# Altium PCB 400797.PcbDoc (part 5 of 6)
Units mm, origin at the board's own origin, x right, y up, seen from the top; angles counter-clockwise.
Board outline 155 x 63.5 mm, 4 copper layers (Top Layer, Mid-Layer 1, Mid-Layer 2, Bottom Layer), stack 1.514 mm thick; 317 components, 286 nets, 1519 pads, 2174 vias.
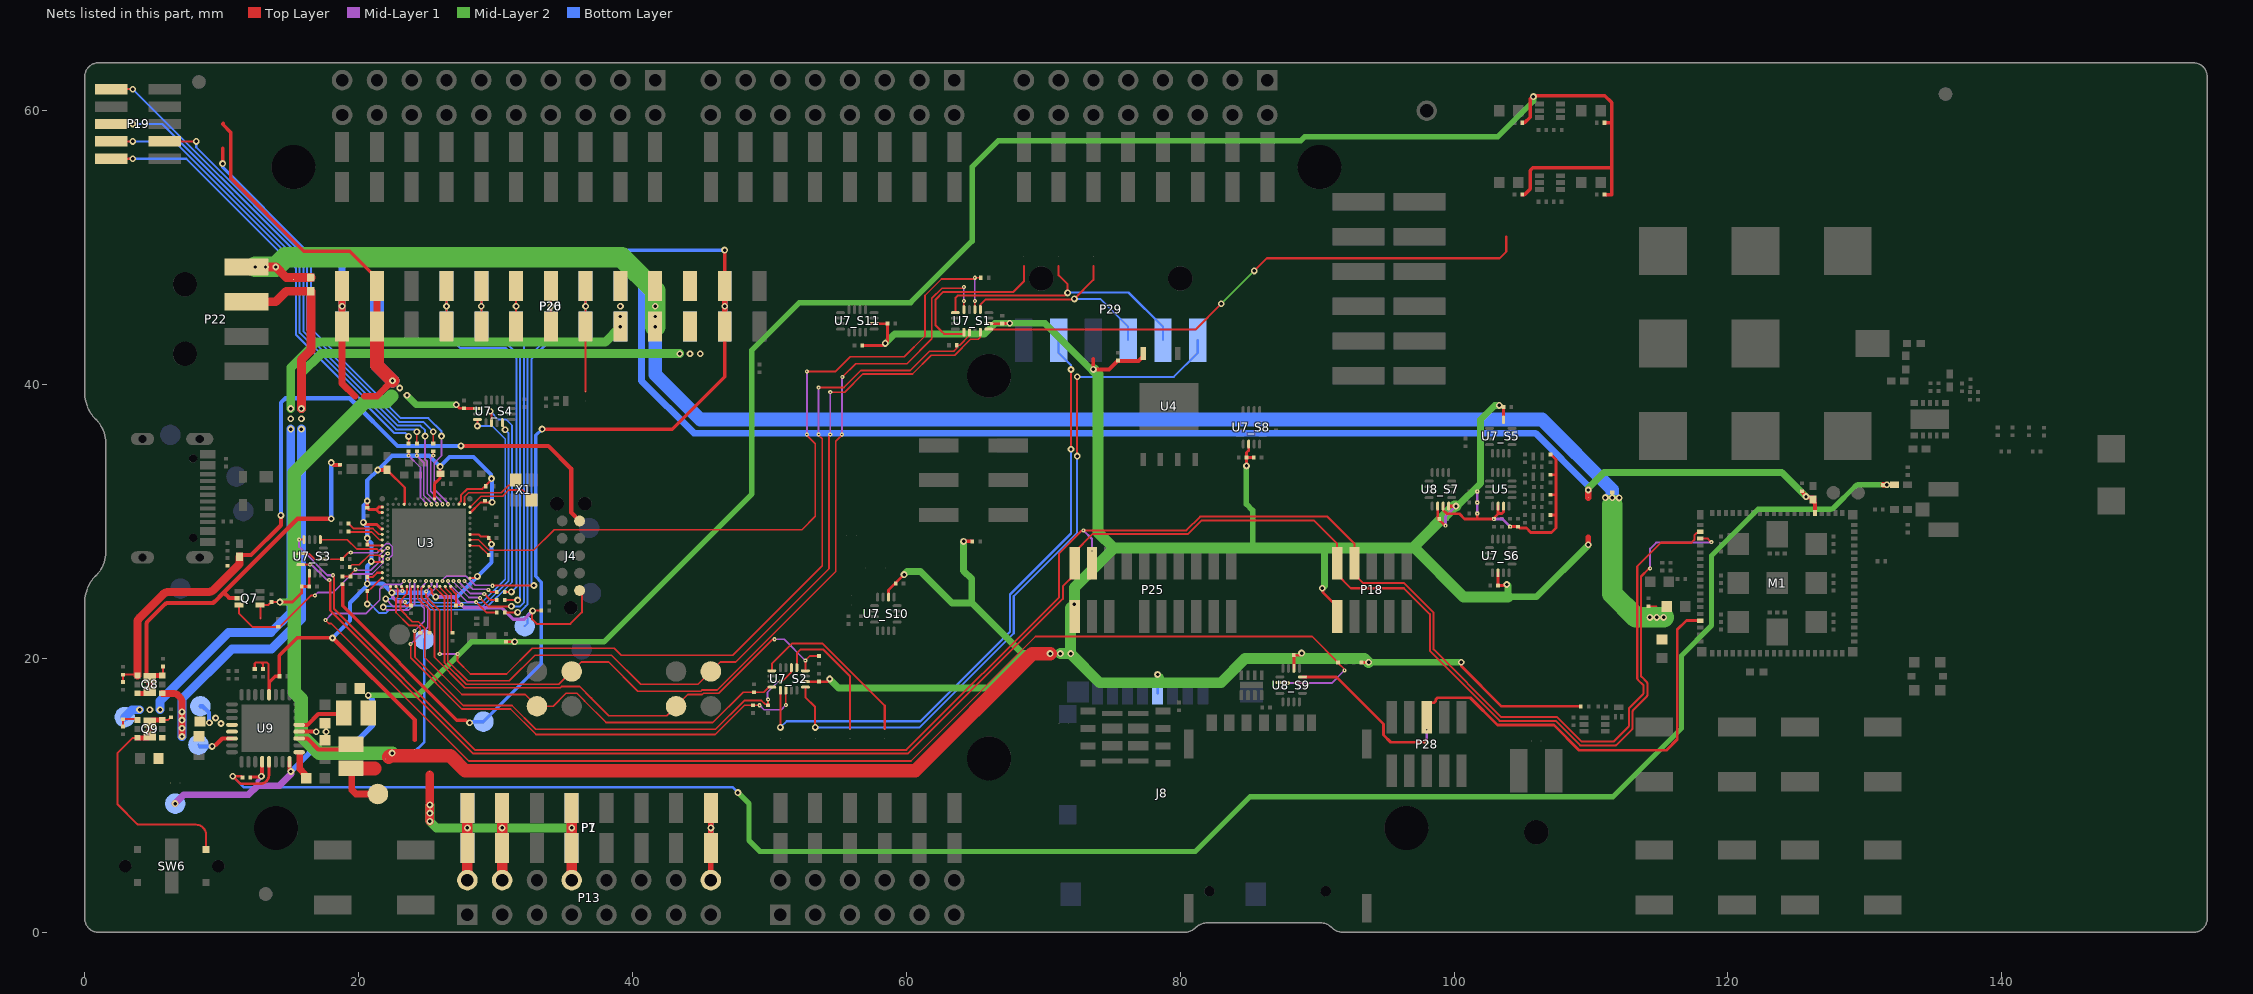
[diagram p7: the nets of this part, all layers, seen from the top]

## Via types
v1: diameter 0.5, hole 0.25, Top Layer to Bottom Layer, tented both sides, 1623 vias
v2: diameter 0.3, hole 0.1, Top Layer to Mid-Layer 1, tented top, 445 vias
v3: diameter 0.3, hole 0.1, Top Layer to Mid-Layer 1, tented both sides, 97 vias
v4: diameter 0.61, hole 0.305, Top Layer to Bottom Layer, tented both sides, 9 vias

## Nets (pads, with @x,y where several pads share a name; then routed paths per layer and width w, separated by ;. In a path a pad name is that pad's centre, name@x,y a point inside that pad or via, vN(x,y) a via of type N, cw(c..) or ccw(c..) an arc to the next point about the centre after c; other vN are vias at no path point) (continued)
SIM_RST: M1.16 P28.6 U8_S9.12 | length 43.8
  Top Layer w0.203: U8_S9.12@88.925,18.65 91.403,18.65 94.853,15.2 94.853,14.406 95.377,13.883 97.874,13.883 97.883,13.873 97.925,13.873 97.974,13.825 v2(98,13.825) ; P28.6@98,15.7 98,16.482 98.278,16.76 98.544,16.76 98.663,16.879 98.663,16.994 98.796,17.127 101.18,17.127 103.168,15.138 107.285,15.138 109.125,13.298 115.498,13.298 116.3,14.1 116.3,22.1 116.974,22.774 117.952,22.774 M1.16@117.975,22.75
  Mid-Layer 1 w0.203: v2(98,13.825) v2(98,14.8)
SIM_SELECT: R63.1 U3.AK8 U8_S9.2 | length 96.1
  Top Layer w0.125: v2(17.575,22.8) 17.825,22.55 18.004,22.55 28.041,12.513 60.337,12.513 69.426,21.602 89.628,21.602 91.552,19.678 91.552,19.648 91.967,19.233 91.967,19.158 v2(92,19.125) ; U8_S9.2@87.275,18.25 87.8,18.25 v2(87.85,18.2)
  Mid-Layer 1 w0.125: v2(17.575,22.8) 18.063,23.288 20.557,23.288 21.537,24.269 21.537,25.046 21.892,25.4 23.066,25.4 v2(23.325,25.659) ; v2(87.85,18.2) 91.075,18.2 v2(92,19.125)
SW1: L7.2 U9.3 | length 4.4
  Top Layer w0.3: U9.3@15.65,14.15 16.25,14.15 17.05,13.35 19.04,13.35 19.45,13.76 L7.2@19.5,13.76
SW2: L8.2 U9.5 | length 3.6
  Top Layer w0.3: U9.5@15.65,15.15 16.25,15.15 17.05,15.95 18.865,15.95 L8.2@18.915,16
SWD0.RESET: P19.10 R30.2 | length 37.6
  Top Layer w0.125: R30.2@25.45,35.694 v1(25.45,36.55)
  Top Layer w0.15: P19.10@1.936,61.571 v1(3.505,61.571)
  Bottom Layer w0.15: v1(3.505,61.571) 16.235,48.84 16.235,44.001 22.961,37.275 24.725,37.275 v1(25.45,36.55)
SWD0.SWDCLK: P19.4 R29.2 | length 34.8
  Top Layer w0.125: R29.2@24.25,35.694 v1(24.25,36.55)
  Top Layer w0.15: P19.4@1.936,57.761 v1(3.505,57.761)
  Bottom Layer w0.15: v1(3.505,57.761) 6.537,57.761 15.685,48.613 15.685,43.773 22.733,36.725 24.075,36.725 v1(24.25,36.55)
SWD0.SWDIO: P19.2 R28.2 | length 33.5
  Top Layer w0.125: R28.2@23.65,35.694 v1(23.65,36.219)
  Top Layer w0.15: P19.2@1.936,56.491 v1(3.505,56.491)
  Bottom Layer w0.15: v1(3.505,56.491) 7.418,56.491 15.41,48.499 15.41,43.659 22.619,36.45 23.419,36.45 v1(23.65,36.219)
SWD0_CLK: R29.1 U3.B18 | length 4.3
  Top Layer w0.125: v2(24.25,34.809) R29.1@24.25,35.124
  Mid-Layer 1 w0.125: v2(24.25,34.809) 24.762,34.297 24.762,31.897 25.063,31.597 25.065,31.597 25.262,31.399 25.262,31.397 25.325,31.334 v2(25.325,31.259)
SWD0_IO: R28.1 U3.B16 | length 4.4
  Top Layer w0.125: v2(23.65,34.809) R28.1@23.65,35.124
  Mid-Layer 1 w0.125: v2(23.65,34.809) 24.512,33.947 24.512,31.749 24.862,31.399 24.862,31.322 v2(24.925,31.259)
SWD0_RESET: R30.1 U3.B22 | length 4.3
  Top Layer w0.125: v2(25.45,34.809) R30.1@25.45,35.124
  Mid-Layer 1 w0.125: v2(25.45,34.809) 25.262,34.622 25.262,32.199 26.063,31.399 26.063,31.347 26.125,31.284 v2(26.125,31.259)
SWD0_SEL: P19.3 U3.B24 | length 38
  Top Layer w0.15: P19.3@5.836,57.761 v1(8.139,57.761)
  Mid-Layer 1 w0.125: v1(26.05,36.234) 26.05,34.809 25.512,34.272 25.512,32.349 26.462,31.399 26.462,31.322 v2(26.525,31.259)
  Bottom Layer w0.15: v1(8.139,57.761) 8.139,57.325 16.51,48.954 16.51,44.115 23.075,37.55 25.086,37.55 26.05,36.586 v1(26.05,36.234)
SWD0_SWO: P19.6 U3.B20 | length 40.8
  Top Layer w0.15: P19.6@1.936,59.031 v1(3.505,59.031)
  Mid-Layer 1 w0.125: v1(24.85,36.234) 24.85,34.563 25.012,34.4 25.012,32.049 25.662,31.399 25.662,31.347 25.725,31.284 v2(25.725,31.259)
  Bottom Layer w0.15: v1(3.505,59.031) 5.656,59.031 15.96,48.726 15.96,43.887 22.847,37 24.5,37 24.85,36.65 v1(24.85,36.234)
SWD1.RESET: P20.7 P26.7 R27.2 | length 28.8
  Top Layer w0.15: R27.2@30.66,23.359 v1(31.609,23.359) ; P20.7@34.036,44.256 v1(34.036,45.721) P20.7@34.036,47.186
  Bottom Layer w0.15: v1(31.609,23.359) 31.759,23.359 32.2,23.8 32.2,23.825 32.338,23.962 32.338,41.972 34.036,43.671 P26.7@34.036,44.256 v1(34.036,45.721) P26.7@34.036,47.186
SWD1.SWDCLK: P20.5 P26.5 R26.2 | length 29.3
  Top Layer w0.15: P20.5@28.956,43.689 P20.5@28.956,44.256 P20.5@28.956,47.186 ; R26.2@30.66,24.259 v1(31.609,24.259)
  Bottom Layer w0.15: P26.5@28.956,47.186 v1(28.956,45.721) 28.956,43.671 29.666,42.961 30.864,42.961 31.788,42.038 31.788,24.438 v1(31.609,24.259)
SWD1.SWDIO: P20.4 P26.4 R25.2 | length 29.9
  Top Layer w0.15: P20.4@26.416,44.349 P20.4@26.416,47.186 ; R25.2@30.66,24.859 v1(31.159,24.859)
  Bottom Layer w0.15: P26.4@26.416,47.186 v1(26.416,45.721) P26.4@26.416,44.256 26.416,43.671 27.401,42.686 30.75,42.686 31.513,41.924 31.513,25.213 v1(31.159,24.859)
SWD1_CLK: R26.1 U3.AK28 | length 3.4
  Top Layer w0.15: v2(29.176,24.71) 29.627,24.259 R26.1@30.09,24.259
  Mid-Layer 1 w0.125: v2(27.325,25.659) 27.325,25.612 27.387,25.549 27.387,25.519 28.16,24.747 29.015,24.747 29.019,24.744 29.143,24.744 v2(29.176,24.71)
SWD1_IO: R25.1 U3.AK30 | length 2.7
  Top Layer w0.15: v2(29.477,25.011) 29.628,24.859 R25.1@30.09,24.859
  Mid-Layer 1 w0.125: v2(27.725,25.659) 28.336,25.048 29.316,25.048 29.319,25.044 29.443,25.044 v2(29.477,25.011)
SWD1_RESET: R27.1 U3.AK24 | length 4.6
  Top Layer w0.15: v2(28.575,24.109) 29.325,23.359 R27.1@30.09,23.359
  Mid-Layer 1 w0.125: v2(26.525,25.659) 26.558,25.626 26.558,25.497 27.937,24.118 28.566,24.118 v2(28.575,24.109)
SWD1_SEL: P20.8 P26.8 SB17.2 U3.AK22 | length 39.5
  Top Layer w0.15: v2(29.777,25.311) 32.786,25.311 v1(32.8,25.325) ; SB17.2@36.576,39.486 SB17.2@36.576,39.498 P20.8@36.576,44.256 v1(36.576,45.721) P20.8@36.576,47.186
  Mid-Layer 1 w0.125: v2(26.125,25.659) 26.125,25.706 26.187,25.769 26.187,25.799 26.385,25.997 27.865,25.997 28.513,25.348 29.616,25.348
  Bottom Layer w0.15: v1(32.8,25.325) 32.613,25.513 32.613,41.859 33.715,42.961 35.866,42.961 36.576,43.671 P26.8@36.576,44.256 v1(36.576,45.721) P26.8@36.576,47.186
SWD1_SWO: P20.6 P26.6 U3.AK26 | length 32.8
  Top Layer w0.15: v2(28.876,24.41) 29.476,23.809 v1@31,23.809 ; P20.6@31.496,43.613 v1(31.496,45.721) P20.6@31.496,47.186
  Mid-Layer 1 w0.125: v2(26.925,25.659) 26.925,25.582 28.06,24.447 28.715,24.447 28.718,24.443 28.842,24.443 v2(28.876,24.41)
  Bottom Layer w0.15: v1(31.159,23.809) 31.795,23.809 32.063,24.076 32.063,43.105 31.496,43.671 P26.6@31.496,44.256 v1(31.496,45.721) P26.6@31.496,47.186
SWD3_CLK: R20.1 U3.R1 | length 2.7
  Top Layer w0.125: R20.1@19.26,29.259 19.26,29.244 19.27,29.234 20.946,29.234 21.521,28.659 U3.R1@21.725,28.659
SWD3_IO: R19.1 U3.N1 | length 2.8
  Top Layer w0.125: R19.1@19.26,29.859 19.26,29.844 19.333,29.772 19.348,29.772 19.635,29.484 21.05,29.484 21.475,29.059 U3.N1@21.725,29.059
SWD3_RESET: R22.1 U3.AA1 | length 2.8
  Top Layer w0.125: R22.1@19.36,26.684 19.514,26.838 20.056,26.838 20.758,27.54 21.444,27.54 21.525,27.459 U3.AA1@21.725,27.459
SWD3_SWO: U3.W1 U7_S3.5 | length 4.9
  Top Layer w0.125: U7_S3.5@17.2,28.675 19.174,28.675 19.852,27.997 21.341,27.997 21.479,27.859 U3.W1@21.725,27.859
SWD_CTRL: R24.2 U3.AB2 U7_S3.2 U7_S3.10 | length 8.5
  Top Layer w0.125: U7_S3.10@15.775,27.65 16.4,27.65 16.8,27.25 U7_S3.2@17.425,27.25 18.765,27.25 19.24,27.725 v2(19.425,27.725)
  Mid-Layer 1 w0.125: v2(19.425,27.725) 21.349,27.725 21.996,28.372 22.254,28.372 22.45,28.176 22.45,27.542 22.167,27.259 v2(22.125,27.259)
SWDCLK: M1.3 P18.4 P25.4 U7_S3.8 | length 144.5
  Top Layer w0.15: v2(15.65,28.675) U7_S3.8@16,28.675 ; v2(18.125,26.075) 18.154,26.046 18.154,25.916 18.2,25.87 18.2,23.616 28.491,13.325 60,13.325 71.15,24.475 71.15,27.678 72.792,29.32 72.898,29.32 v2(72.927,29.348) 80.446,29.348 81.45,30.353 90.752,30.353 92.73,28.375 P18.4@92.73,26.95 92.73,26.13 93.335,25.525 96.317,25.525 98.5,23.342 98.5,20.662 103.447,15.715 107.524,15.715 109.314,13.925 111.588,13.925 ccw(c111.588,14.075) 111.694,13.969 112.721,14.996 ccw(c112.615,15.102) 112.765,15.102 112.765,16.303 cw(c112.915,16.303) 112.809,16.409 113.797,17.397 ccw(c113.69,17.503) 113.84,17.503 113.84,17.972 ccw(c113.69,17.972) 113.797,18.078 113.419,18.456 cw(c113.525,18.562) 113.375,18.562 113.375,26.726 115.099,28.45 117.333,28.45 117.55,28.668 117.55,28.82 117.55,28.983 117.742,29.175 117.9,29.175 M1.3@117.975,29.25
  Mid-Layer 1 w0.15: v2(15.65,28.675) 15.65,28.145 17.72,26.075 v2(18.125,26.075) ; v2(72.927,29.348) 73.555,28.72 v2(73.555,27.85)
SWDIO: M1.4 P18.2 P25.2 U7_S3.12 | length 142.7
  Top Layer w0.15: U7_S3.12@15.775,26.85 v2@16.375,26.85 ; v2(16.45,26.85) v2@16.375,26.85 ; v2@16.45,26.925 v2@16.375,26.85 ; v2(17.85,25.725) 17.85,25.684 17.925,25.609 17.925,23.502 28.377,13.05 60.114,13.05 71.425,24.361 71.425,25.27 72.285,26.13 P25.2@72.285,26.95 72.285,27.77 73.588,29.073 80.559,29.073 81.564,30.078 89.757,30.078 91.46,28.375 P18.2@91.46,26.95 91.46,26.13 92.465,25.125 96.328,25.125 98.225,23.228 98.225,20.548 103.333,15.44 107.41,15.44 109.2,13.65 111.763,13.65 ccw(c111.763,13.8) 111.869,13.694 112.996,14.821 ccw(c112.89,14.927) 113.04,14.927 113.04,14.995 113.04,16.128 cw(c113.19,16.128) 113.084,16.234 114.072,17.222 ccw(c113.965,17.328) 114.115,17.328 114.115,18.172 ccw(c113.965,18.172) 114.072,18.278 ; 114.072,18.278 113.694,18.656 cw(c113.8,18.762) 113.65,18.762 113.65,25.983 114.217,26.55 114.292,26.55 v3(114.321,26.579) ; M1.4@117.975,28.75 118.528,28.75 v3(118.786,28.491)
  Mid-Layer 1 w0.15: v2(16.45,26.85) 16.556,26.85 17.656,25.75 17.825,25.75 v2(17.85,25.725) ; v3(114.321,26.579) 114.321,28.021 114.763,28.463 118.758,28.463 v3(118.786,28.491)
TGT_SCL: U3.AK12 U7_S4.4 | length 26.2
  Top Layer w0.125: U7_S4.4@30.5,37.225 30.5,36.984 30.7,36.784 v1(30.7,36.7)
  Mid-Layer 1 w0.125: v1(21.8,23.75) 22.013,23.538 23.665,23.538 24.075,23.947 24.075,25.609 v2(24.125,25.659)
  Bottom Layer w0.125: v1(21.8,23.75) 21.857,23.807 23.311,23.807 23.617,24.113 25.034,24.113 25.34,23.807 29.078,23.807 30.95,25.679 30.95,36.439 30.7,36.689 v1(30.7,36.7)
TGT_SDA: U3.AK10 U7_S4.16 | length 26.5
  Top Layer w0.125: v1(28.675,36.975) U7_S4.16@28.675,37.45
  Mid-Layer 1 w0.125: v1(21.975,24.35) 22.538,23.788 23.541,23.788 23.725,23.971 v2(23.725,25.659)
  Bottom Layer w0.125: v1(21.975,24.35) 23.501,24.35 23.514,24.363 25.138,24.363 25.444,24.057 28.974,24.057 30.7,25.782 30.7,36.025 29.75,36.975 v1(28.675,36.975)
TGT_TWI_CTRL: R31.1 U3.AJ1 U7_S4.2 | length 28.8
  Top Layer w0.125: v1(20.625,23.975) 20.635,23.985 20.635,24.85 21.063,25.278 21.643,25.859 U3.AJ1@21.725,25.859 ; v1(29.6,38.05) 29.7,37.95 U7_S4.2@29.7,37.225
  Bottom Layer w0.125: v1(20.625,23.975) 20.836,23.975 21.498,23.313 21.981,23.313 22.225,23.557 23.415,23.557 23.721,23.863 24.931,23.863 25.237,23.557 29.182,23.557 31.2,25.575 31.2,37.025 30.775,37.45 30.2,37.45 v1(29.6,38.05)
UART1.CTS: P29.6 SB6.2 U7_S2.13 | length 51.7
  Top Layer w0.15: U7_S2.13@52.625,17.9 52.625,17.17 53.34,16.455 v1(53.34,14.962) ; v1(72.475,34.775) v1(72.475,40.566)
  Bottom Layer w0.15: v1(53.34,14.962) 60.967,14.962 67.842,21.837 67.842,24.554 72.475,29.186 v1(72.475,34.775) ; v1(72.475,40.566) 79.541,40.566 81.28,42.305 P29.6@81.28,43.25
UART1.RTS: P29.2 SB5.2 U7_S2.9 | length 46.2
  Top Layer w0.15: SB5.2@50.8,14.838 SB5.2@50.8,14.85 v1(50.8,14.962) U7_S2.9@50.8,17.675 U7_S2.9@50.8,17.875 ; v1(72.025,35.275) v1(72.025,41.1)
  Bottom Layer w0.15: v1(50.8,14.962) 51.25,15.412 61.028,15.412 67.567,21.951 67.567,24.667 72.025,29.125 v1(72.025,35.275) ; P29.2@71.12,43.25 71.12,42.305 72.025,41.4 v1(72.025,41.1)
UART1.RXD: P29.4 SB3.2 U7_S1.1 | length 16.1
  Top Layer w0.15: U7_S1.1@65.4,45.475 65.4,45.818 65.807,46.225 72.24,46.225 v1(72.268,46.253) 73.66,47.645 SB3.2@73.66,48.65 SB3.2@73.66,48.662
  Bottom Layer w0.15: v1(72.268,46.253) 74.172,46.253 74.221,46.204
  Bottom Layer w0.152: 74.221,46.204 76.2,44.225 P29.4@76.2,43.25
UART1.TXD: P29.5 SB4.2 U7_S1.5 | length 20.6
  Top Layer w0.15: U7_S1.5@63.575,45.25 63.575,46.325 63.75,46.5 71.575,46.5 v1(71.775,46.7) 71.775,47.325 71.12,47.98 SB4.2@71.12,48.662
  Bottom Layer w0.15: v1(71.775,46.7) 71.8,46.725 76.225,46.725 78.74,44.21 P29.5@78.74,43.25
UART2.CTS: SB10.2 U7_S2.5 | length 13
  Top Layer w0.15: U7_S2.5@50.175,19.1 50.175,19.623 51.652,21.1 53.864,21.1 58.42,16.544 SB10.2@58.42,14.85 SB10.2@58.42,14.838
UART2.RTS: SB9.2 U7_S2.1 | length 9.7
  Top Layer w0.15: U7_S2.1@52,19.325 52,20.375 52.288,20.663 53.912,20.663 55.88,18.695 SB9.2@55.88,14.85 SB9.2@55.88,14.838
UART2.RXD: SB7.2 U7_S1.9 | length 12.4
  Top Layer w0.15: U7_S1.9@64.2,43.825 64.2,43.74 64.162,43.702 62.755,43.702 62.55,43.907 62.55,43.914 62.125,44.339 62.125,46.194 62.706,46.775 67.825,46.775 68.58,47.53 SB7.2@68.58,48.65 SB7.2@68.58,48.662
UART2.TXD: SB8.2 U7_S1.13 | length 41.2
  Top Layer w0.15: U7_S1.13@66.025,44.05 66.05,44.025 81.125,44.025 v1(83,45.9) ; v1(85.4,48.3) 86.325,49.225 103.325,49.225 103.81,49.71 SB8.2@103.81,50.801
  Mid-Layer 2 w0.15: v1(83,45.9) v1(85.4,48.3)
USB_DETECT: Q7.3 R74.2 SB29.2 U3.Y2 | length 14.4
  Top Layer w0.15: Q7.3@11.25,23.9 11.25,23.311 12.274,22.288 13.178,22.288 R74.2@14.125,22.288 ; R74.2@14.125,22.315 14.24,22.315 16.525,24.6 v2(16.8,24.6)
  Mid-Layer 1 w0.125: v2(16.8,24.6) 17.012,24.812 18.157,24.812 19.507,26.163 20.972,26.163 21.775,26.966 21.775,27.433 22.001,27.659 v2(22.125,27.659)
VBUS: Q7.2 Q8.3 Q8.6 R21.1 R78.2 | length 30.4
  Top Layer w0.15: Q8.6@5.655,18.75 5.7,18.795 R78.2@5.7,19.415
  Top Layer w0.3: Q8.6@4.75,18.575 4.5,18.825 4.5,22.476 cw(c4.8,22.476) 4.588,22.688 5.862,23.962 cw(c6.074,23.75) 6.074,24.05 9.268,24.05 ccw(c9.268,24.35) 9.48,24.138 10.148,24.805 ; Q7.2@11.25,24.4 10.553,24.4 10.148,24.805 ; v1(18,30.2) 15.542,30.2 10.148,24.805 ; v1(18,34.3) 18.165,34.135 R21.1@18.625,34.135
  Top Layer w0.35: Q8.3@3.845,17.45 4.575,17.45 Q8.3@4.75,17.625 ; Q8.6@4.75,18.575 4.925,18.75 Q8.6@5.655,18.75
  Top Layer w0.5: Q8.3@4.75,17.625 Q8.6@4.75,18.575
  Bottom Layer w0.3: v1(18,30.2) v1(18,34.3)
VBUS': C51.2 FB2.2 J4.5 Q8.1 R76.1 R77.1 | length 55.7
  Top Layer w0.15: R77.1@2.8,18.285 R76.1@2.8,18.815 Q8.1@3.78,18.815
  Top Layer w0.2: Q8.1@3.78,18.815 Q8.1@3.845,18.75
  Top Layer w0.3: FB2.2@11.3,27.425 11.3,27.45 11.4,27.55 12.15,27.55 14.325,29.725 v1(14.325,30.45) ; v1(27.475,35.525) 33.85,35.525 35.525,33.85 35.525,30.65 J4.5@36.135,30.04
  Top Layer w0.6: Q8.1@3.845,18.75 3.845,22.571 cw(c4.445,22.571) 4.02,22.995 5.7,24.675 cw(c6.124,24.25) 6.124,24.85 9.001,24.85 ccw(c9.001,25.45) 9.426,25.026 11.3,26.9 FB2.2@11.3,27.425
  Bottom Layer w0.3: v1(14.325,30.45) 14.325,38.675 14.65,39 19.35,39 22.825,35.525 v1(27.475,35.525)
VBUSOUT: TP25.1 U9.22 | length 2.4
  Top Layer w0.3: 9.564,13.675 10.039,14.15 U9.22@10.75,14.15
  Bottom Layer w0.15: TP25.1@8.3,13.7 TP25.1@8.425,13.575
  Bottom Layer w0.3: TP25.1@8.425,13.575 v1(9.3,13.575)
VCOM0_CTRL: R13.1 U3.R31 U7_S1.2 | length 57
  Top Layer w0.125: U3.R31@28.125,28.659 28.754,28.659 29.516,27.896 32.771,27.896 34.275,29.4 52.375,29.4 53.35,30.375 53.35,35.685 52.737,36.298 v2(52.737,36.35) ; v2(52.737,40.963) 54.841,40.963 55.904,42.025 59.839,42.025 61.362,43.548 61.362,46.509 62.566,47.713 64.913,47.713 v2(65,47.8) R13.1@65.44,47.8 ; U7_S1.2@65,45.475 v2(65,46.1)
  Mid-Layer 1 w0.125: v2(52.737,36.35) v2(52.737,40.963) ; v2(65,46.1) v2(65,47.8)
VCOM0_CTS: R86.1 TP5.1 U3.AL9 U7_S2.8 | length 35.9
  Top Layer w0.125: U3.AL9@23.525,25.259 23.525,24.717 23.062,24.254 23.062,23.548 23.923,22.688 24.366,22.688 24.838,22.216 24.838,20.072 27.547,17.363 32.168,17.363 32.822,16.708 32.822,16.312 TP5.1@33.02,16.51 34.201,16.51 35.139,17.448 35.948,17.448 36.498,16.898 36.498,16.895 38.07,15.323 45.858,15.323 48.076,17.54 R86.1@48.875,17.54 49.59,17.54 49.95,17.9 U7_S2.8@50.175,17.9
VCOM0_HWFC: R17.1 U3.AK16 U7_S2.2 | length 38.7
  Top Layer w0.125: v2(24.075,22.004) 24.075,21.217 24.113,21.179 24.113,20.09 27.64,16.563 31.198,16.563 32.938,14.823 46.065,14.823 48.165,16.923 49.425,16.923 49.69,16.658 49.828,16.658 R17.1@49.9,16.585 v2(49.9,17) ; v2(50.8,18.3) 50.9,18.3 51.6,19 U7_S2.2@51.6,19.325
  Mid-Layer 1 w0.125: v2(24.075,22.004) 24.788,22.716 24.788,23.658 24.587,23.858 24.587,25.237 24.853,25.503 24.853,25.54 24.925,25.612 v2(24.925,25.659) ; v2(49.9,17) 49.862,17.038 49.862,17.54 50.623,18.3 v2(50.8,18.3)
VCOM0_RTS: R15.1 U3.AL5 | length 4.6
  Top Layer w0.125: U3.AL5@22.725,25.259 22.725,25.235 22.862,25.097 22.862,24.488 22.725,24.35 22.725,23.351 23.663,22.413 24.288,22.413 24.5,22.2 R15.1@24.5,21.869
VCOM0_RXD: TP4.1 U3.AL19 U7_S1.4 | length 69.7
  Top Layer w0.125: U3.AL19@25.525,25.217 25.542,25.217 26.262,24.497 26.262,20.465 26.263,20.185 26.262,19.708 27.858,18.113 34.622,18.113 TP4.1@35.56,19.05 36.248,19.738 38.262,19.738 40.388,17.613 44.991,17.613 45.076,17.698 46.194,17.698 54.85,26.354 54.85,35.86 55.288,36.298 v2(55.288,36.35) ; v2(55.325,40.55) 56.3,41.525 60.046,41.525 61.862,43.341 61.862,46.302 62.598,47.038 64.088,47.038 v2@64.175,47.125 ; U7_S1.4@64.2,45.475 v2(64.2,46.1)
  Top Layer w0.15: U3.AL19@25.525,25.217 U3.AL19@25.525,25.259
  Mid-Layer 1 w0.125: v2(55.288,36.35) 55.306,36.369 55.306,40.531 v2(55.325,40.55) ; v2@64.175,47.125 64.2,47.1 v2(64.2,46.1)
  other v2: 64.2,47.125
VCOM0_TXD: R11.1 U3.U31 | length 1.7
  Top Layer w0.125: U3.U31@28.125,28.259 28.144,28.24 28.819,28.24 R11.1@29.5,27.559
VCOM1_CTRL: R14.2 U3.AK18 U7_S1.10 | length 64.5
  Top Layer w0.125: v2@24.925,24.925 v2(24.925,24.9) 24.925,24.475 25.925,23.475 v2(25.925,20.325) ; v2(27.225,20.325) 27.225,19.806 28.169,18.863 30.8,18.863 32.675,20.738 38.677,20.738 39.177,20.238 47.32,20.238 53.85,26.768 53.85,36.035 53.588,36.298 v2(53.588,36.35) ; v2@53.588,39.75 53.625,39.788 55.438,39.788 56.675,41.025 60.275,41.025 61.688,42.438 63.459,42.438 63.661,42.639 63.661,42.851 R14.2@63.685,42.875 63.886,42.875 64.6,43.589 U7_S1.10@64.6,43.825
  Mid-Layer 1 w0.125: v2@24.925,24.925 25.325,25.325 v2(25.325,25.659) ; v2(25.925,20.325) v2(27.225,20.325) ; v2(53.588,36.35) v2(53.588,39.775)
VCOM1_CTS: R85.1 TP9.1 U3.AL15 U7_S2.16 | length 39.4
  Top Layer w0.125: U3.AL15@24.725,25.259 24.725,25.235 24.575,25.085 24.575,24.471 25.538,23.509 25.538,20.079 27.754,17.863 34.726,17.863 34.811,17.948 36.152,17.948 36.155,17.948 36.998,17.105 36.998,17.102 38.277,15.823 42.492,15.823 TP9.1@43.18,16.51 44.032,17.363 45.095,17.363 45.18,17.448 46.298,17.448 50.25,21.4 v2(50.375,21.4) ; v2(52.625,19.85) 52.96,20.185 R85.1@53.625,20.185
  Top Layer w0.15: U7_S2.16@52.625,19.1 v2(52.625,19.85)
  Mid-Layer 1 w0.125: v2(50.375,21.4) 51.075,21.4 v2(52.625,19.85)
VCOM1_HWFC: R18.2 U3.AK20 U7_S2.10 | length 38.4
  Top Layer w0.125: v2(23.8,21.05) 23.8,20.049 27.537,16.313 31.095,16.313 32.957,14.45 46.046,14.45 48.181,16.585 v2(49.285,16.585) ; v2(51.2,16.6) U7_S2.10@51.2,17.675
  Mid-Layer 1 w0.125: v2(23.8,21.05) 25.038,22.288 25.038,24.535 25.725,25.223 v2(25.725,25.659) ; v2(49.285,16.585) 49.608,16.263 50.862,16.263 v2(51.2,16.6)
VCOM1_RTS: R16.1 U3.AL13 | length 3.7
  Top Layer w0.125: U3.AL13@24.325,25.259 24.325,24.368 25.175,23.518 R16.1@25.175,21.869
VCOM1_RXD: TP8.1 U3.AL21 U7_S1.12 | length 65.2
  Top Layer w0.125: U3.AL21@25.925,25.235 25.925,25.188 25.976,25.138 ; 25.976,25.137 26.512,24.6 26.512,20.568 26.513,20.082 26.512,19.811 27.961,18.363 31.007,18.363 32.882,20.238 38.47,20.238 40.595,18.113 44.782,18.113 TP8.1@45.72,19.05 46.408,19.738 47.527,19.738 54.35,26.561 54.35,36.263 v2(54.438,36.35) ; v2(54.438,39.45) 55.5,39.45 56.825,40.775 60.45,40.775 61.825,42.15 63.525,42.15 64.687,43.313 65.257,43.313 65.4,43.455 U7_S1.12@65.4,43.825
  Mid-Layer 1 w0.125: v2(54.438,36.35) v2(54.438,39.45)
VCOM1_TXD: R12.1 U3.AL23 | length 3.6
  Top Layer w0.125: U3.AL23@26.325,25.259 26.344,25.24 26.344,25.122 26.762,24.704 26.762,21.932 R12.1@26.825,21.869
VDD: C42.2 C52_S1.1 C52_S2.1 C52_S3.1 C52_S4.1 C52_S5.1 C52_S6.1 C52_S8.1 C52_S10.1 C52_S11.1 C53_S7.1 C53_S9.1 J8.4 P18.1 P20.2 P25.1 P26.2 Q7.4 R8.1 R23.2 R35.2 R62.1 R66.1 R69.2 R75.1 SB1.1 SB16.2 SB20.1 SB29.1 SB30.2 SB31.1 SB32.1 SB33.2 TP23.1 U4.8 U7_S1.14 U7_S2.14 U7_S3.14 U7_S4.14 U7_S5.14 U7_S6.14 U7_S8.14 U7_S10.14 U7_S11.14 U8_S7.14 U8_S7.16 U8_S9.14 | length 355.1
  Top Layer w0.15: 12.825,22.912 SB29.1@12.825,22.95 12.825,23.875 Q7.4@12.8,23.9 13.41,23.9 R75.1@13.625,24.115 v1(14.25,24.115)
  Top Layer w0.2: v1(14.25,24.115) 15.165,24.115 15.835,24.785 C52_S3.1@15.835,25.25 R23.2@16.335,25.25 ; R23.2@16.39,25.25 R23.2@16.335,25.25 ; U7_S3.14@16.4,26.225 16.4,25.315 R23.2@16.335,25.25 ; v1(27.125,38.525) 27.385,38.265 C52_S4.1@27.7,38.265 27.715,38.25 U7_S4.14@28.675,38.25 ; U7_S2.14@52.625,18.3 54.2,18.3 v1(54.4,18.5) ; R66.1@56.785,42.85 58.3,42.85 v1(58.458,43.008) 58.615,43.165 C52_S11.1@58.615,44.45 U7_S11.14@57.643,44.45 ; U7_S10.14@58.7,24.475 58.7,24.993 v1(59.832,26.125) ; U7_S1.14@66.025,44.45 66.985,44.45 C52_S1.1@67,44.465 67.54,44.465 v1(67.55,44.475) ; v1(84.838,34.062) C52_S8.1@84.838,34.671 ; U7_S8.14@85,35.65 85,35.193 84.838,35.031 C52_S8.1@84.838,34.671 ; R35.2@85.368,34.671 C52_S8.1@84.838,34.671 ; U8_S9.14@88.3,19.275 88.3,20.235 v1@88.86,20.235 ; v1(90.375,25.125) 90.432,25.068 90.432,24.818 91.46,23.79 P18.1@91.46,23.05 ; R62.1@93.235,19.7 v1@93.752,19.7 ; U8_S7.14@98.8,31.125 98.8,30.225 99.325,29.7 v2(99.375,29.7) v2@99.4,29.7 ; v1(100.525,19.718) 100.525,19.45 103.475,16.5 R8.1@109.255,16.5 ; U7_S6.14@103.21,26.259 103.208,26.257 C52_S6.1@103.208,25.334 103.217,25.325 103.775,25.325 v1(103.85,25.4)
  Top Layer w0.22: v1(103.3,38.475) 103.376,38.475 103.452,38.399 103.588,38.399 103.61,38.377 U7_S5.14@103.61,37.434
  Top Layer w0.25: v1(73.66,41.11) SB20.1@73.66,41.855 73.66,41.893
  Top Layer w0.254: SB16.2@10.1,59.095 10.062,59.057 10.062,59 10.675,58.387 10.675,55.075 16,49.75 19.35,49.75 21.336,47.764 P20.2@21.336,46.949 ; v1(64.176,28.55) R69.2@64.815,28.55 ; U8_S7.16@99.6,31.125 v1(100.137,31.125)
  Top Layer w0.3: v1(73.66,41.11) 74.795,41.11 75.41,41.725 76.95,41.725 77.282,42.057 U4.8@77.282,42.27
  Top Layer w0.4: v1(109.8,28.3) SB1.1@109.8,28.85
  Top Layer w0.5: 20.404,39.148 21.337,39.148 v1(22.47,40.28)
  Top Layer w0.508: P20.2@21.336,44.256 P20.2@21.336,46.949
  Top Layer w1: P20.2@21.336,44.256 21.336,41.414 v1(22.47,40.28) ; 22.2,12.8 22.3,12.9 25.195,12.9 26.678,12.9 27.778,11.8 60.65,11.8 69.2,20.35 v1(70.5,20.35)
  Mid-Layer 1 w0.2: v2(99.375,29.7) 99.375,30.363 v1(100.137,31.125)
  Mid-Layer 2 w0.4: v1(84.838,34.062) 84.838,31.265 85.282,30.821 85.282,28.05
  Mid-Layer 2 w0.5: v1(14.25,24.115) 15.29,24.115 15.3,24.125 ; v1(23.53,39.22) 24.225,38.525 v1(27.125,38.525) ; v1(54.4,18.5) 55.05,17.85 65.975,17.85 68.475,20.35 ; v1(58.458,43.008) 59.15,43.7 65.7,43.7 66.475,44.475 v1(67.55,44.475) 70.125,44.475 73.49,41.11 v1(73.66,41.11) ; v1(59.832,26.125) 60.057,26.35 61.025,26.35 63.325,24.05 64.775,24.05 ; v1(64.176,28.55) 64.176,26.399 64.775,25.8 64.775,24.05 ; v1(70.5,20.35) 68.475,20.35 ; v1(78.35,18.825) 78.58,18.595 78.58,18.225 ; v1(88.86,20.385) 89.13,20.115 89.13,20 ; v1(90.375,25.125) 90.53,25.28 90.53,28.05 ; v1(93.752,19.718) v1(100.525,19.718) ; v1(100.137,31.125) 100.259,31.125 101.925,32.791 101.925,37.431 102.969,38.475 v1(103.3,38.475) ; v1(103.85,25.4) 103.93,25.32 103.93,24.5 106,24.5 v1(109.8,28.3) ; 64.775,24.05 68.475,20.35
  Mid-Layer 2 w0.8: v1(71.25,20.35) 71.975,20.35 74.1,18.225 78.58,18.225 82.968,18.225 84.743,20 89.13,20 93.47,20 v1(93.752,19.718) ; v1(72,20.35) 72,23.675 v1(72.275,23.95) 72.275,25.17 75.155,28.05 ; v1(73.66,41.11) 74,40.77 74,29.205 75.155,28.05 ; v1(100.137,31.125) 100.025,31.125 96.95,28.05 ; 103.93,24.5 100.693,24.5 97.143,28.05 96.95,28.05 ; 75.155,28.05 85.282,28.05 90.53,28.05 96.95,28.05
  Mid-Layer 2 w1: 22.4,39.15 22,38.75 20.5,38.75 15.3,33.55 15.3,24.125 15.3,17.543 15.8,17.043 15.8,14.4 17.116,13.084 v1(22.444,13.084)
  Bottom Layer w0.2: v1(22.444,13.084) 22.616,13.084 22.62,13.08 23.354,13.08 23.358,13.084 23.984,13.084 24.795,13.895 TP23.1@24.795,21.38 ; J8.4@78.35,17.47 v1(78.35,18.825)
  Bottom Layer w1: P26.2@21.336,47.186 P26.2@21.336,44.256 21.336,41.414 v1(22.47,40.28)
  other v1: 23,39.75
VDD_1V8: C60.2 L7.1 SB33.1 TP21.1 U9.1 | length 8.9
  Top Layer w0.3: U9.1@15.65,13.15 15.65,11.9 C60.2@16.275,11.275
  Top Layer w0.5: 15.7,12.9 15.7,11.92 C60.2@16.05,11.57 ; L7.1@19.45,11.965 19.5,11.915 19.5,10.393 19.793,10.1 TP21.1@21.4,10.1
  Top Layer w1: L7.1@19.45,11.965 21.165,11.965
VDD_3V0: C59.2 L8.1 R33.2 R39.2 R40.2 R41.2 R42.2 R87.1 TP27.1 U9.28 U9.32 | length 160
  Top Layer w0.2: R87.1@12.085,11.3 12.085,11.315 12.12,11.35 12.85,11.35 v1(12.9,11.4) ; R33.2@30.75,21.215 v1(31.39,21.215)
  Top Layer w0.25: R41.2@104.983,53.868 105.143,53.868 105.556,54.281 105.556,55.632 105.747,55.823 111.496,55.823 ; R39.2@104.983,59.118 105.143,59.118 105.556,59.531 105.556,60.882 ; v1(105.79,61.033) 105.856,61.1 111,61.1 111.499,60.601 111.499,53.868 R42.2@110.983,53.868 ; R40.2@110.983,59.118 111.499,59.118
  Top Layer w0.3: v1(12.9,11.4) 12.95,11.45 U9.28@12.95,12.45 ; U9.32@14.95,12.45 14.95,11.896 15.048,11.798 v1(15.048,11.744)
  Mid-Layer 1 w0.3: 12.6,10.7 12.6,11.046 12.9,11.346 v1(12.9,11.4)
  Mid-Layer 1 w0.5: v1(6.6,9.4) 7.25,10.05 11.95,10.05 12.6,10.7 14.184,10.7 15.048,11.564 v1(15.048,11.744)
  Mid-Layer 2 w0.4: v1(20.7,17.3) 24.313,17.3 28.228,21.215 v1(31.39,21.215) 37.915,21.215 48.714,32.014 48.714,42.514 52.189,45.989 60.311,45.989 64.8,50.479 64.8,55.9 66.7,57.8 88.8,57.8 89.1,58.1 103.2,58.1 105.8,60.7 105.8,61 105.79,61.01 v1(105.79,61.033)
  Bottom Layer w0.4: v1(15.048,11.744) 16.404,13.1 19,13.1 21,15.1 21,17 v1(20.7,17.3)
VDD_5V: C54.2 C58.2 P20.11 P22.2 P26.11 Q8.4 Q9.4 R82.2 SB34.2 SB35.1 U9.21 | length 76.7
  Top Layer w0.5: Q8.4@5.655,17.45 6.468,17.45 cw(c6.468,16.95) 6.821,17.304 6.954,17.171 cw(c6.6,16.818) 7.1,16.818 v1(7.1,16.1) v1(7.1,15.5) v1(7.1,14.9) v1(7.1,14.3)
  Top Layer w0.65: P22.2@11.811,46.049 13.946,46.049 14.716,46.819 R82.2@16.51,46.819 16.51,42.491 15.819,41.8 v1(15.819,38.25)
  Mid-Layer 2 w0.65: v1(15.819,38.25) 15.819,40.819 17.256,42.256 v1(43.446,42.256)
  Bottom Layer w0.65: v1(7.1,14.3) v1(7.1,14.9) v1(7.1,15.5) 7.1,15.903 7.1,17.04 10.76,20.7 13.651,20.7 15.819,22.867 v1(15.819,36.75)
  other v1: 15.819,37.5 44.196,42.256 44.946,42.256
VDD_GNSS: C11.2 L3.1 R87.2 U9.29 | length 147.6
  Top Layer w0.2: R87.2@11.515,11.3 11.415,11.4 v1(10.8,11.4) 10.9,11.3 11.291,10.909 ccw(c11.433,11.05) 11.433,10.85 12.825,10.85 ccw(c12.825,11.475) 13.45,11.475 U9.29@13.45,12.45 ; C11.2@131.315,32.68 C11.2@131.318,32.68 ; v1@131.66,32.68 L3.1@132.155,32.68
  Top Layer w0.381: C11.2@131.318,32.68 131.601,32.68 v1(131.606,32.685)
  Mid-Layer 2 w0.381: v1(47.7,10.2) 48.5,9.4 48.5,6.7 49.3,5.9 81.1,5.9 85.1,9.9 111.6,9.9 116.6,14.9 116.6,20.2 118.8,22.4 118.8,27.5 122.2,30.9 127.467,30.9 ccw(c127.467,31.281) 127.736,31.011 129.299,32.574 cw(c129.568,32.304) 129.568,32.685 v1(131.606,32.685)
  Bottom Layer w0.2: v1(10.8,11.4) 11.6,10.6 47.3,10.6 v1(47.7,10.2)
VDD_GPIO: C4.1 C5.1 M1.65 P20.1 P26.1 SB2.1 SB31.2 | length 136.1
  Top Layer w0.305: C4.1@125.4,32.185 125.602,31.983 125.602,31.97 125.7,31.872 v1(125.7,31.819) ; v1@125.691,31.8 125.753,31.8 125.805,31.748 126.202,31.748 126.3,31.65 126.3,31.4 126.35,31.35 M1.65@126.35,30.625
  Top Layer w0.5: 18.796,41.891 18.796,40.08 SB31.2@19.728,39.148 ; SB2.1@109.8,31.75 v1(109.8,32.3)
  Top Layer w0.508: 18.796,41.891 P20.1@18.796,44.256 P20.1@18.796,47.186
  Mid-Layer 2 w0.5: v1(109.8,32.3) 109.8,32.45 110.937,33.587 123.933,33.587 v1(125.7,31.819)
  Bottom Layer w0.5: P26.1@18.796,47.186 18.796,48.821 19.3,49.325 39.575,49.325 40.65,48.25 40.65,40.275 44.479,36.446 105.929,36.446 109.8,32.575 v1(109.8,32.3)
  Bottom Layer w0.508: P26.1@18.796,44.256 P26.1@18.796,47.186
  other v1: 18.796,45.721
VDD_IMCU: C24.2 C25.2 C26.1 C27.2 C28.1 C31.2 C32.2 C33.2 C34.1 C35.2 C62.1 J4.1 R34.2 R83.2 R84.2 SB32.2 TP12.1 U3.A19 U3.AC1 U3.AG1 U3.AJ31 U3.AL3 U3.AL7 U3.AL11 U3.AL17 U3.AL25 U3.B8 U3.B28 U3.C1 U3.E1 U3.E31 U3.L1 U3.N31 U3.U1 U9.12 | length 105
  Top Layer w0.15: R84.2@12.412,19.227 12.412,19.612 12.5,19.7 12.9,19.7 ; R83.2@13.012,19.227 13.012,19.588 12.9,19.7 ; 13.46,18.26 13.4,18.319 13.4,19.6 13.3,19.7 12.9,19.7 ; v1@20.635,25.459 C26.1@20.635,25.959 ; C25.2@20.635,28.259 U3.U1@21.725,28.259 ; C25.2@20.635,28.334 v1@20.635,28.784 ; C26.1@20.65,25.959 21.05,25.959 21.35,26.259 U3.AG1@21.725,26.259 ; v1@20.925,27.059 U3.AC1@21.725,27.059 ; v1@22.325,24.794 U3.AL3@22.325,25.259 ; v2(23.2,24.923) U3.AL7@23.2,25.184 ; v2(23.375,24.125) 23.375,24 23.506,23.869 C27.2@23.827,23.869 23.838,23.88 23.838,25.151 23.925,25.239 U3.AL11@23.925,25.259 ; U3.AL17@25.125,25.217 25.34,25.002 25.34,24.779 v1(25.625,24.494) ; U3.AL25@26.725,25.259 26.725,25.113 27.1,24.738 C31.2@27.1,23.869 27.125,23.894 27.475,23.894 v2(27.5,23.919) ; U3.B28@27.325,31.259 27.325,31.334 27.462,31.472 27.462,31.916 27.918,32.372 29.013,32.372 29.141,32.5 29.23,32.5 29.261,32.531 29.261,32.62 29.7,33.059 v1(29.7,33.134) ; U3.AJ31@28.125,25.859 28.443,25.859 ; U3.N31@28.125,29.059 28.75,29.059 28.9,28.909 C32.2@29.49,28.909 ; U3.E31@28.125,30.659 28.167,30.659 28.892,31.384 v1@29.75,31.384 ; C32.2@29.428,28.847 29.634,28.64 29.634,28.4 v1(29.7,28.334) ; R34.2@33.34,23.5 32.725,23.5 v1(32.7,23.475) 32.675,23.45 32.675,22.85 33,22.525 35.467,22.525 36.3,23.359 36.3,24.795 J4.1@36.135,24.96
  Top Layer w0.187: C35.2@22.175,33.839 22.175,33.667 23.368,32.474 23.368,31.302 U3.B8@23.325,31.259
  Top Layer w0.2: v1(20.35,29.934) 20.5,29.784 21.323,29.784 21.648,29.459 U3.L1@21.725,29.459 ; C24.2@20.625,30.994 20.644,30.959 ccw(c20.809,31.072) 20.809,30.872 21.287,30.872 ; U3.E1@21.725,30.659 21.72,30.664 21.495,30.664 21.287,30.872 ; U3.C1@21.725,31.059 21.475,31.059 21.287,30.872
  Top Layer w0.225: U3.A19@25.525,31.659 25.525,32.754 25.95,33.179 v1(25.95,34.009)
  Top Layer w0.25: U9.12@13.45,17.35 13.46,17.36 13.46,18.26 13.9,18.7 C62.1@14.215,18.7 14.215,20.215 15.516,21.516 18.066,21.516 v1(18.091,21.491) ; C24.2@20.625,30.994 20.619,31 20.619,31.492 v1(20.625,31.497)
  Top Layer w0.3: v1(18.091,21.491) 18.109,21.491 24.1,15.5 SB32.2@24.1,14.05 ; v1(21.4,33.759) C35.2@22.025,33.759
  Mid-Layer 1 w0.25: v1(22.423,24.794) 22.475,24.742 22.475,24.467 22.817,24.125 v2(23.375,24.125) ; v1@22.527,24.923 v2(23.2,24.923) ; v1(25.625,24.494) 26.925,24.494 v2(27.5,23.919) 27.71,23.709 30.441,23.709 31.291,22.859 32.084,22.859 v1(32.7,23.475)
  Bottom Layer w0.15: TP12.1@32.129,22.353 32.343,22.567 32.343,23.218 32.533,23.408 32.633,23.408 v1(32.7,23.475)
  Bottom Layer w0.3: v1(18.091,21.491) 19.375,22.775 19.375,24.067 20.587,25.279 20.587,25.367 v1@20.625,25.367 ; v1(29.7,28.334) 29.7,27.022 v1(28.675,25.997) 27.173,24.494 v1(25.625,24.494) 25.571,24.494 25.271,24.794 v1(22.423,24.794) 21.758,25.459 v1(20.625,25.459) 20.625,26.734 20.925,27.034 v1(20.925,27.088) 20.925,28.43 20.625,28.73 v1(20.625,28.784) 20.625,29.605 20.35,29.88 v1(20.35,29.934) 20.35,31.168 20.625,31.443 v1(20.625,31.497) 20.625,32.984 v1(21.4,33.759) 22.441,34.8 25.159,34.8 v1(25.95,34.009) 26.641,34.7 28.4,34.7 29.662,33.438 29.662,33.172 v1(29.7,33.134) 29.725,33.109 29.725,31.434 v1(29.75,31.409)
VDD_nRF: C1.1 C2.1 C3.1 FB1.1 P20.10 P22.1 P26.10 R82.1 SB34.1 | length 127.1
  Top Layer w0.125: C1.1@114.19,23.815 114.8,23.815
  Top Layer w0.65: P22.1@11.811,48.589 v1(12.446,48.589) v1(13.196,48.589) v1(13.946,48.589) 14.716,47.819 R82.1@16.51,47.819
  Mid-Layer 2 w1.5: v1(12.446,48.589) v1(13.196,48.589) v1(13.946,48.589) 14.657,49.3 39.2,49.3 41.656,46.844 v1(41.656,45.721) v1(41.656,44.971) v1(41.656,44.221) ; 111.55,31.226 111.55,24.725 113.28,22.995 v1(114.298,22.995) ; v1@114.298,22.992 115.301,22.992 v1(115.305,22.996)
  Bottom Layer w1: P26.10@41.656,44.256 v1(41.656,44.221) 41.656,40.742 44.948,37.45 106.425,37.45 111.55,32.325 v1@111.55,31.85
  other v1: 114.8,23 112.053,31.729 111.048,31.745 111.55,31.75
VIN: P1.8 P7.8 P13.16 | length 8.2
  Top Layer w0.381: P13.16@45.72,3.811 P1.8@45.72,6.156 v1(45.72,7.621) P1.8@45.72,9.086
  Bottom Layer w0.381: P7.8@45.72,6.156 v1(45.72,7.621) P7.8@45.72,9.086
VIN_5V: Q9.3 Q9.6 R81.1 SW6.6 | length 17.9
  Top Layer w0.15: Q9.3@3.845,14.2 3.492,14.2 2.4,13.108 2.4,11.6 2.4,9.331 3.827,7.904 ccw(c3.933,8.01) 3.933,7.86 8.115,7.86 cw(c8.115,7.125) 8.85,7.125 SW6.6@8.85,6.035 ; Q9.6@5.655,15.5 6.07,15.5 6.285,15.715 R81.1@6.3,15.715
  Top Layer w0.35: Q9.3@3.845,14.2 4.575,14.2 Q9.3@4.75,14.375 ; Q9.6@4.75,15.325 4.925,15.5 Q9.6@5.655,15.5
  Top Layer w0.5: Q9.3@4.75,14.375 Q9.6@4.75,15.325
VIN_5V': P20.9 P26.9 Q9.1 R79.2 R80.1 TP22.1 | length 57.4
  Top Layer w0.15: R79.2@2.8,15.035 R80.1@2.8,15.565 Q9.1@3.78,15.565
  Mid-Layer 2 w0.65: v1(15.044,38.25) 15.044,41.244 16.9,43.1 37.995,43.1 v1(39.116,44.221)
  Bottom Layer w0.65: TP22.1@2.921,15.718 3.453,16.25 v1(4,16.25) ; v1(5.5,16.25) 5.5,16.9 10.5,21.9 13.6,21.9 15.044,23.344 v1(15.044,36.75)
  other v1: 4.75,16.25 15.044,37.5 39.116,44.971 39.116,45.721
VIO: P1.1 P1.2 P1.4 P7.1 P7.2 P7.4 P13.2 P13.4 P13.8 SB30.1 | length 39.8
  Top Layer w0.4: v1@25.195,8.105 v1(25.2,8.1)
  Top Layer w0.6: v1@25.195,8.105 v1@25.195,9.3 ; v1(25.2,9.3) 25.2,11.5
  Top Layer w0.75: P13.2@27.94,3.811 P1.1@27.94,6.156 P1.1@27.94,9.086 ; P13.4@30.48,3.811 P1.2@30.48,9.086 ; P13.8@35.56,3.811 P1.4@35.56,9.086
  Mid-Layer 2 w0.65: v1(25.2,9.3) v1(25.2,8.7) v1(25.2,8.1) 25.679,7.621 v1(27.94,7.621) v1(30.48,7.621) v1(35.56,7.621)
  Bottom Layer w0.762: P7.1@27.94,6.156 P7.1@27.94,9.086 ; P7.2@30.48,6.156 P7.2@30.48,9.086 ; P7.4@35.56,6.156 P7.4@35.56,9.086
VIO_REF: P20.12 P26.12 R64.1 SB15.2 TP16.1 | length 107.1
  Top Layer w0.25: v1(10.062,56.138) 10.062,57.25 ; R64.1@18.825,25.415 18.825,23.839 27.164,15.5 27.832,15.5 28.032,15.3 v1(28.1,15.3) ; v1(33.4,36.75) 42.9,36.75 46.736,40.586 P20.12@46.736,44.256 ; v1@46.7,49.825 46.736,49.789 P20.12@46.736,46.991
  Top Layer w0.381: P20.12@46.736,44.256 v1(46.736,45.721) P20.12@46.736,46.991
  Bottom Layer w0.25: v1(10.062,56.138) 10.062,55.861 16.099,49.825 v1@46.7,49.825 ; v1(28.1,15.3) 28.186,15.386 TP16.1@29.108,15.386 33.35,19.627 33.35,25.575 32.938,25.988 32.938,36.288 v1(33.4,36.75) ; P26.12@46.736,47.186 P26.12@46.736,47.764
  Bottom Layer w0.381: P26.12@46.736,44.256 v1(46.736,45.721) P26.12@46.736,47.186
  other v1: 46.725,49.825
VIO_REF_SENSE: R64.2 R65.2 U3.V2 | length 4.6
  Top Layer w0.125: R64.2@18.825,25.985 R65.2@19.4,25.985 19.4,26.125 v2(19.775,26.5)
  Mid-Layer 1 w0.125: v2(19.775,26.5) 19.838,26.438 20.893,26.438 21.525,27.069 21.525,27.536 21.985,27.997 22.015,27.997 22.078,28.059 v2(22.125,28.059)
VIOEXT: C43.2 R48.2 R49.2 R50.2 R51.2 R52.2 R54.2 R56.2 R58.2 R60.2 U5.14 U5.15 U8_S7.15 | length 20.1
  Top Layer w0.2: U8_S7.15@99.2,31.125 99.204,31.121 99.204,30.832 99.461,30.575 100.375,30.575 100.775,30.175 101.725,30.175 ; v2(101.688,30.572) 101.688,30.212 101.725,30.175 ; U5.14@103.21,31.125 103.21,30.55 ; U5.15@103.61,31.125 103.61,30.696 103.492,30.578 103.238,30.578 103.21,30.55 ; 101.725,30.175 v2(102.906,30.175) C43.2@102.927,30.197 102.927,30.267 103.21,30.55
  Top Layer w0.203: v2(104.095,29.627) R51.2@104.68,29.627 104.777,29.529 105.276,29.529 105.6,29.205 107.118,29.205 107.448,29.534 107.448,31.959 ; R52.2@107.048,30.476 107.443,30.476 ; R54.2@107.048,31.949 107.438,31.949 107.448,31.959 ; R56.2@107.048,33.422 107.437,33.422 ; R60.2@107.048,34.896 107.083,34.896 107.448,34.531 107.448,31.959
  Mid-Layer 1 w0.2: v2(101.688,30.572) v2(101.688,31.385) v2(101.688,32.198)
  Mid-Layer 1 w0.203: v2(102.906,30.175) 103.547,30.175 v2(104.095,29.627)
VSYS: C55.2 C56.2 C57.2 TP26.1 U9.4 U9.20 | length 2.7
  Top Layer w0.3: U9.4@15.65,14.65 v1@16.796,14.65
  Bottom Layer w0.3: TP26.1@8.44,16.51 8.59,16.51 9.06,16.04 9.06,15.394 9.1,15.354 v1(9.1,15.3)
  other v1: 16.9,14.65 17.625,14.65 9.95,15.25 9.55,15.65
XC1: U3.C31 X1.1 | length 5.3
  Top Layer w0.125: U3.C31@28.125,31.059 28.149,31.059 28.937,31.847 30.513,31.847 30.963,32.297 31.984,32.297 32.625,31.656 X1.1@32.625,31.588
XC2: U3.B30 X1.3 | length 4.6
  Top Layer w0.125: U3.B30@27.725,31.259 27.725,31.807 28.027,32.109 30.421,32.109 30.955,32.643 31.113,32.643 X1.3@31.36,32.891
pads on no net: D5. D5.4 Fid1.0 Fid2.0 Fid3.0 J4.0 J4.6 J4.7 J4.8 J4.9 J5. J5.C6 J6. J6.0 J6.13 J6.A8 J6.B8 J8.10 M1.26 M1.31 M1.32 M1.33 M1.37 M1.81 M1.82 M1.83 M1.84 M1.85 M1.86 M1.87 M1.88 M1.89 M1.90 M1.91 M1.92 M1.93 M1.94 M1.95 M1.96 M1.97 M1.98 M1.100 M1.102 M1.103 M1.104 P18.7 P18.8 P19.7 P19.8 P19.9 P22.0 P22.3 P25.11 P25.13 P28.3 P28.7 P28.8 P28.9 P28.10 P29.0 P30.0 SW6.0 U2. U3. U3.A1 U3.A21 U3.A31 U3.AG31 U3.AK2 U3.AK4 U3.AK6 U3.AL1 U3.AL31 U3.B10 U3.D2 U3.F2 U3.J1 U3.K2 U3.L31 U3.M2 U3.P2 U3.T2 U4.3 U4.7 U6.0 U6.4 U6.5 U8_S7.10 U8_S9.10 U9.7 U9.8 U9.9 U9.10 U9.11 U9.15 U9.18 U9.19 U9.23 U9.24 U9.25 U9.26 U9.27
copper on no net:
  other v1: 145.485,13.717 153.534,50.267

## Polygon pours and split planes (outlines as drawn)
GND on Top Layer "Top_Layer-GND" (solid, remove dead copper, pour order 29): 0,0.001 0,63.501 142.284,63.501 142.284,0.001
VDD_nRF on Top Layer "NONET_L-01_P-001" (solid, pour order 27): 114,23.953 115.271,23.953 115.9,23.953 115.9,22.121 cw(c115.609,22.121) 115.815,21.915 115.746,21.846 ccw(c116.082,21.509) 115.606,21.509 115.606,21.005 114.803,21.005 114.8,21.611 ccw(c114.629,21.611) 114.719,21.756 114.114,22.13 cw(c114.24,22.335) 114,22.335
NetC50_2 on Top Layer "VUSB" (solid, pour order 24): 8.9,29.6 10.4,29.6 cw(c10.4,29.4) 10.6,29.4 10.6,28.7 11.6,28.7 11.6,28.1 11,28.1 11,28.3 10,28.3 cw(c10,28.4) 9.9,28.4 9.9,28.9 ccw(c9.8,28.9) 9.8,29 9,29 cw(c9,29.1) 8.9,29.1
GND on Bottom Layer "Bottom_Layer-GND" (solid, remove dead copper, pour order 18): 0,0.001 0,63.501 142.24,63.501 142.24,0.001
GND on Mid-Layer 2 "Mid_Layer_2-GND" (solid, remove dead copper, pour order 28): 0,0.001 0,63.501 155,63.501 155,0.001
GND on Mid-Layer 1 "Mid_Layer_1-GND" (solid, remove dead copper, pour order 22): 0,0.001 0,63.501 155,63.501 155,0.001

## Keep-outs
Top Layer:
  circle w0.152: c13.97,7.621 r2.4
  circle w0.152: c15.24,55.881 r2.4
  circle w0.152: c66.04,12.701 r2.4
  circle w0.152: c66.04,40.641 r2.4
  circle w0.152: c96.52,7.621 r2.4
  region: 109.775,55.15 110.225,55.15 110.225,54.375 109.775,54.375
  region: 103.75,55.15 104.2,55.15 104.2,54.525 103.75,54.525
  region: 139.325,36.725 143.625,36.725 143.625,34.6 139.325,34.6
  region: 115.475,28.05 116.45,28.05 116.45,27.55 115.475,27.55
  region: 116.675,27.55 117.45,27.55 117.45,26.925 116.675,26.925
  lines w0.152: 90.909,53.598 cw(c90.17,55.881) 91.891,54.208
Bottom Layer:
  circle w1.3: c127.127,11.177 r0.01
  circle w1.3: c39.37,16.803 r0.01
  circle w1.3: c22.987,13.965 r0.01
  circle w1.3: c9.869,7.113 r0.01
  circle w1.3: c22.987,13.965 r0.01
  circle w1.3: c34.163,26.544 r0.01
  circle w1.3: c125.476,2.065 r0.01
  circle w1.3: c83.82,14.733 r0.01
  circle w1.3: c86.97,16.15 r0.01
  circle w1.3: c88.804,18.912 r0.01
  circle w1.3: c82.839,19.442 r0.01
  circle w1.3: c53.721,22.079 r0.01
  circle w1.3: c111.379,54.484 r0.01
  circle w1.3: c114.808,48.979 r0.01
  circle w1.3: c113.284,46.61 r0.01
  circle w0.152: c13.97,7.621 r2.4
  circle w0.152: c15.24,55.881 r2.4
  circle w0.152: c66.04,12.701 r2.4
  circle w0.152: c96.52,7.621 r2.4
  lines w0.152: 67.712,42.363 ccw(c66.04,40.641) 68.297,41.458 ; 90.849,53.579 cw(c90.17,55.881) 91.929,54.248
Keep-Out Layer:
  circle w0.152: c79.1,0 r0.173
  circle w0.152: c78.3,0 r0.173
  circle w0.152: c77.5,0 r0.173
  circle w0.152: c76.7,0 r0.173
  circle w0.152: c75.9,0 r0.173
  circle w0.152: c79.1,63.5 r0.173
  circle w0.152: c78.3,63.5 r0.173
  circle w0.152: c77.5,63.5 r0.173
  circle w0.152: c76.7,63.5 r0.173
  circle w0.152: c75.9,63.5 r0.173
  circle w0.152: c141.6,63.5 r0.173
  circle w0.152: c140.8,63.5 r0.173
  circle w0.152: c140,63.5 r0.173
  circle w0.152: c139.2,63.5 r0.173
  circle w0.152: c138.4,63.5 r0.173
  circle w0.152: c141.6,0 r0.173
  circle w0.152: c140.8,0 r0.173
  circle w0.152: c140,0 r0.173
  circle w0.152: c139.2,0 r0.173
  circle w0.152: c138.4,0 r0.173
  circle w0.152: c16.6,0 r0.173
  circle w0.152: c15.8,0 r0.173
  circle w0.152: c15,0 r0.173
  circle w0.152: c14.2,0 r0.173
  circle w0.152: c13.4,0 r0.173
  circle w0.152: c16.6,63.5 r0.173
  circle w0.152: c15.8,63.5 r0.173
  circle w0.152: c15,63.5 r0.173
  circle w0.152: c14.2,63.5 r0.173
  circle w0.152: c13.4,63.5 r0.173
  circle w0.152: c155,51.9 r0.173
  circle w0.152: c155,52.7 r0.173
  circle w0.152: c155,53.5 r0.173
  circle w0.152: c155,54.3 r0.173
  circle w0.152: c155,55.1 r0.173
  circle w0.152: c155,8.4 r0.173
  circle w0.152: c155,9.2 r0.173
  circle w0.152: c155,10 r0.173
  circle w0.152: c155,10.8 r0.173
  circle w0.152: c155,11.6 r0.173
  circle w0.152: c0,8.4 r0.173
  circle w0.152: c0,9.2 r0.173
  circle w0.152: c0,10 r0.173
  circle w0.152: c0,10.8 r0.173
  circle w0.152: c0,11.6 r0.173
  circle w0.152: c0,51.9 r0.173
  circle w0.152: c0,52.7 r0.173
  circle w0.152: c0,53.5 r0.173
  circle w0.152: c0,54.3 r0.173
  circle w0.152: c0,55.1 r0.173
